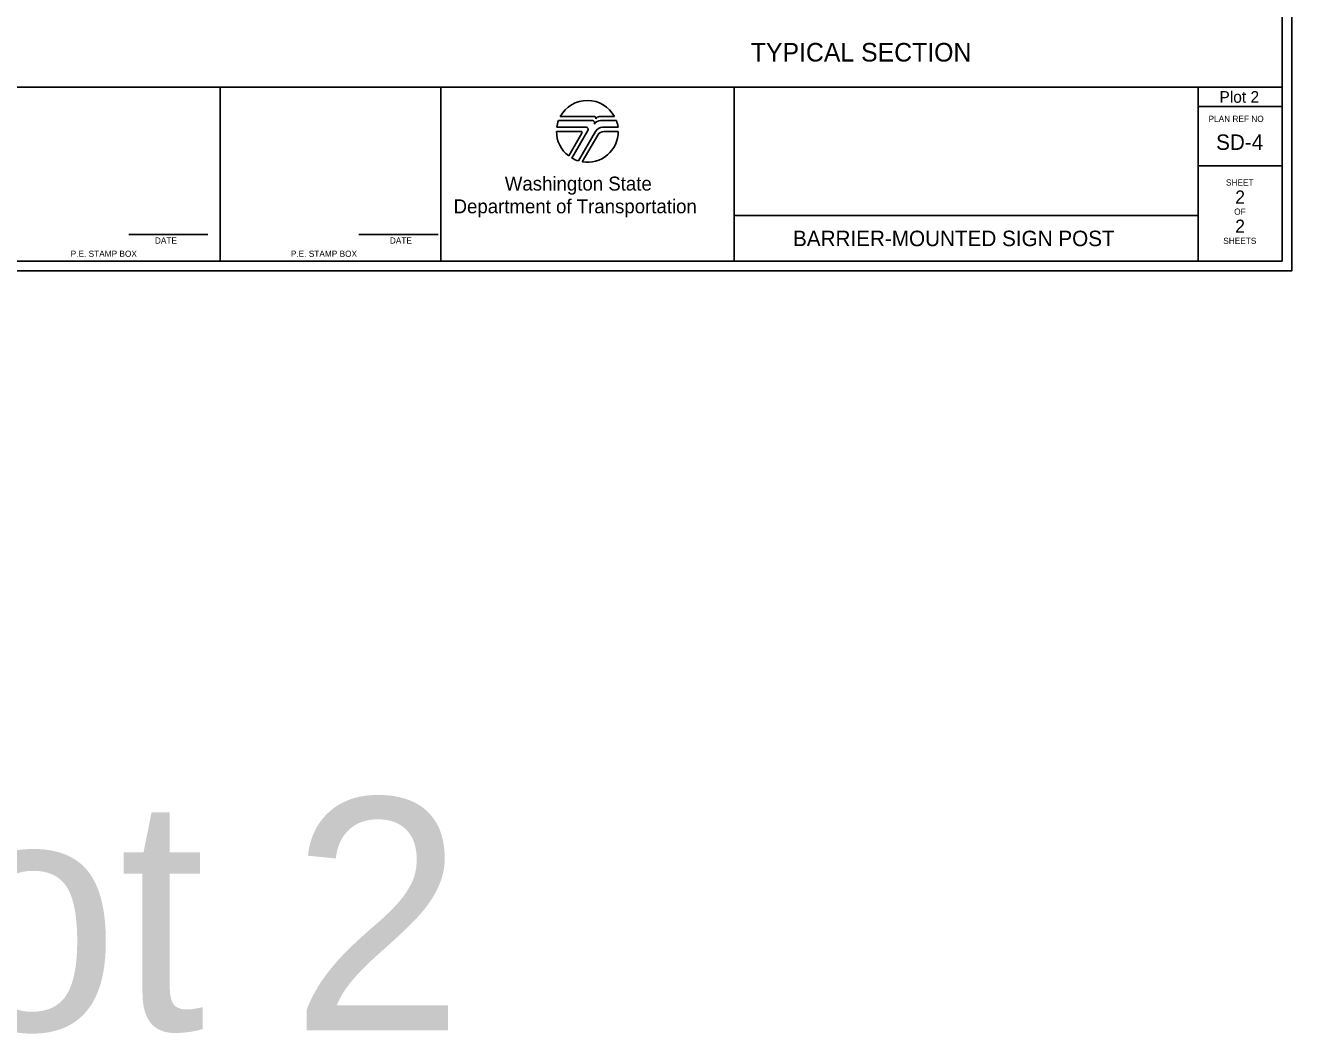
# Model space of a CAD drawing. Extents: x 99988 to 100172, y 99995 to 100047.
# Drawn here: x 100027.62 to 100035.81, y 99995.01 to 100001.53 of the extents above; entities that cross this region are included whole.
import ezdxf

# ---------------------------------------------------------------- set-up
doc = ezdxf.new("R2010")
doc.units = 0
for name, color, linetype in [('Level 20', 7, 'Continuous'), ('SH_GI_PlotLimits', 7, 'Continuous'), ('SH_GI_SheetBorder', 7, 'Continuous'), ('SH_GI_SheetLocationText', 7, 'Continuous'), ('SH_GI_SheetTextInCells', 7, 'Continuous'), ('SH_GI_TitleBlockText', 7, 'Continuous'), ('SH_GI_WSDOTLogo', 7, 'Continuous')]:
    doc.layers.add(name, color=color, linetype=linetype)

msp = doc.modelspace()

# ---------------------------------------------------------------- linework, layer by layer
at = {"layer": 'SH_GI_PlotLimits'}
msp.add_lwpolyline([(100019.3125, 99999.9375), (100035.8125, 99999.9375), (100035.8125, 100010.4375), (100019.3125, 100010.4375)], close=True, dxfattribs=at)
at = {"layer": 'SH_GI_SheetBorder'}
for p, q in [((100035.75, 100010.375), (100035.75, 100000)), ((100020, 100001.1259), (100035.75, 100001.1259)), ((100028.8828, 100000), (100028.8828, 100001.1259)), ((100030.3089, 100001.1259), (100030.3089, 100000)), ((100032.2055, 100001.1259), (100032.2055, 100000)), ((100035.2079, 100001.1259), (100035.2079, 100000)), ((100035.2079, 100001.0008), (100035.75, 100001.0008)), ((100035.2079, 100000.6176), (100035.75, 100000.6176)), ((100032.2055, 100000.2955), (100035.2079, 100000.2955)), ((100028.2903, 100000.1733), (100028.802, 100000.1733)), ((100029.7797, 100000.1733), (100030.2914, 100000.1733)), ((100020, 100000), (100035.75, 100000))]:
    msp.add_line(p, q, dxfattribs=at)
at = {"layer": 'SH_GI_WSDOTLogo'}
for p, q in [((100031.303, 100000.9354), (100031.0815, 100000.9354)), ((100031.433, 100000.9354), (100031.3351, 100000.9354)), ((100031.0572, 100000.84), (100031.2148, 100000.84)), ((100031.059, 100000.8661), (100031.2496, 100000.8661)), ((100031.2894, 100000.9094), (100031.0697, 100000.9094)), ((100031.261, 100000.8464), (100031.1567, 100000.6672)), ((100031.1989, 100000.6487), (100031.3089, 100000.839)), ((100031.343, 100000.9094), (100031.3429, 100000.9094)), ((100031.4448, 100000.9094), (100031.343, 100000.9094)), ((100031.3558, 100000.8661), (100031.4555, 100000.8661)), ((100031.3655, 100000.8394), (100031.4572, 100000.8394)), ((100031.222, 100000.8277), (100031.1364, 100000.6807)), ((100031.2244, 100000.6428), (100031.3242, 100000.8156))]:
    msp.add_line(p, q, dxfattribs=at)
for centre, radius, start, end in [((100031.2572, 100000.84), 0.2, 28.47865, 151.53204), ((100031.303, 100000.9263), 0.00903, 329.87418, 90.00328), ((100031.3352, 100000.9066), 0.0287, 90.00721, 148.16763), ((100031.2572, 100000.84), 0.2, 179.99864, 232.84327), ((100031.2572, 100000.84), 0.2, 159.69598, 172.50569), ((100031.2149, 100000.8318), 0.0082, 329.74356, 90), ((100031.2572, 100000.84), 0.2, 260.54554, 359.80857), ((100031.2497, 100000.853), 0.0131, 329.76834, 90), ((100031.2894, 100000.8946), 0.0148, 327.8418, 89.99855), ((100031.3429, 100000.861), 0.0484, 89.99529, 147.82376), ((100031.3558, 100000.8119), 0.0542, 90, 149.99738), ((100031.3654, 100000.7918), 0.0476, 90, 150.05432), ((100031.2572, 100000.84), 0.2, 7.49431, 20.29406), ((100031.2572, 100000.84), 0.2, 239.79292, 253.0448)]:
    msp.add_arc(centre, radius, start, end, dxfattribs=at)

# ---------------------------------------------------------------- texts
at = {"layer": 'Level 20'}
msp.add_text('TYPICAL SECTION', height=0.12, dxfattribs=at).set_placement((100032.3141, 100001.2915))
at = {"layer": 'SH_GI_SheetBorder'}
msp.add_text('PLAN REF NO', height=0.040032, dxfattribs=at).set_placement((100035.2747, 100000.9008))
at = {"layer": 'SH_GI_SheetLocationText'}
for height, p in [(0.075, (100035.3454, 100001.025)), (1.5, (100025.3275, 99995.0267))]:
    msp.add_text('Plot 2', height=height, dxfattribs=at).set_placement(p)
at = {"layer": 'SH_GI_SheetTextInCells'}
for s, height, p in [('Washington State', 0.090072, (100030.7229, 100000.4571)), ('SHEET', 0.04003, (100035.3877, 100000.4896)), ('Department of Transportation', 0.090072, (100030.3916, 100000.3101)), ('OF', 0.04003, (100035.4406, 100000.3008)), ('DATE', 0.04003, (100028.4597, 100000.1141)), ('DATE', 0.04003, (100029.9794, 100000.1141)), ('SHEETS', 0.04003, (100035.3698, 100000.112)), ('P.E. STAMP BOX', 0.040032, (100027.915, 100000.0286)), ('P.E. STAMP BOX', 0.040032, (100029.339, 100000.0286))]:
    msp.add_text(s, height=height, dxfattribs=at).set_placement(p)
at = {"layer": 'SH_GI_TitleBlockText'}
for s, height, p in [('SD-4', 0.1, (100035.3238, 100000.72)), ('2', 0.085, (100035.4473, 100000.3723)), ('2', 0.085, (100035.4473, 100000.1843)), ('BARRIER-MOUNTED SIGN POST', 0.1, (100032.5871, 100000.0977))]:
    msp.add_text(s, height=height, dxfattribs=at).set_placement(p)

doc.saveas('drawing.dxf')
